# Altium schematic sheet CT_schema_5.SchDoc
size 281 x 146 mm
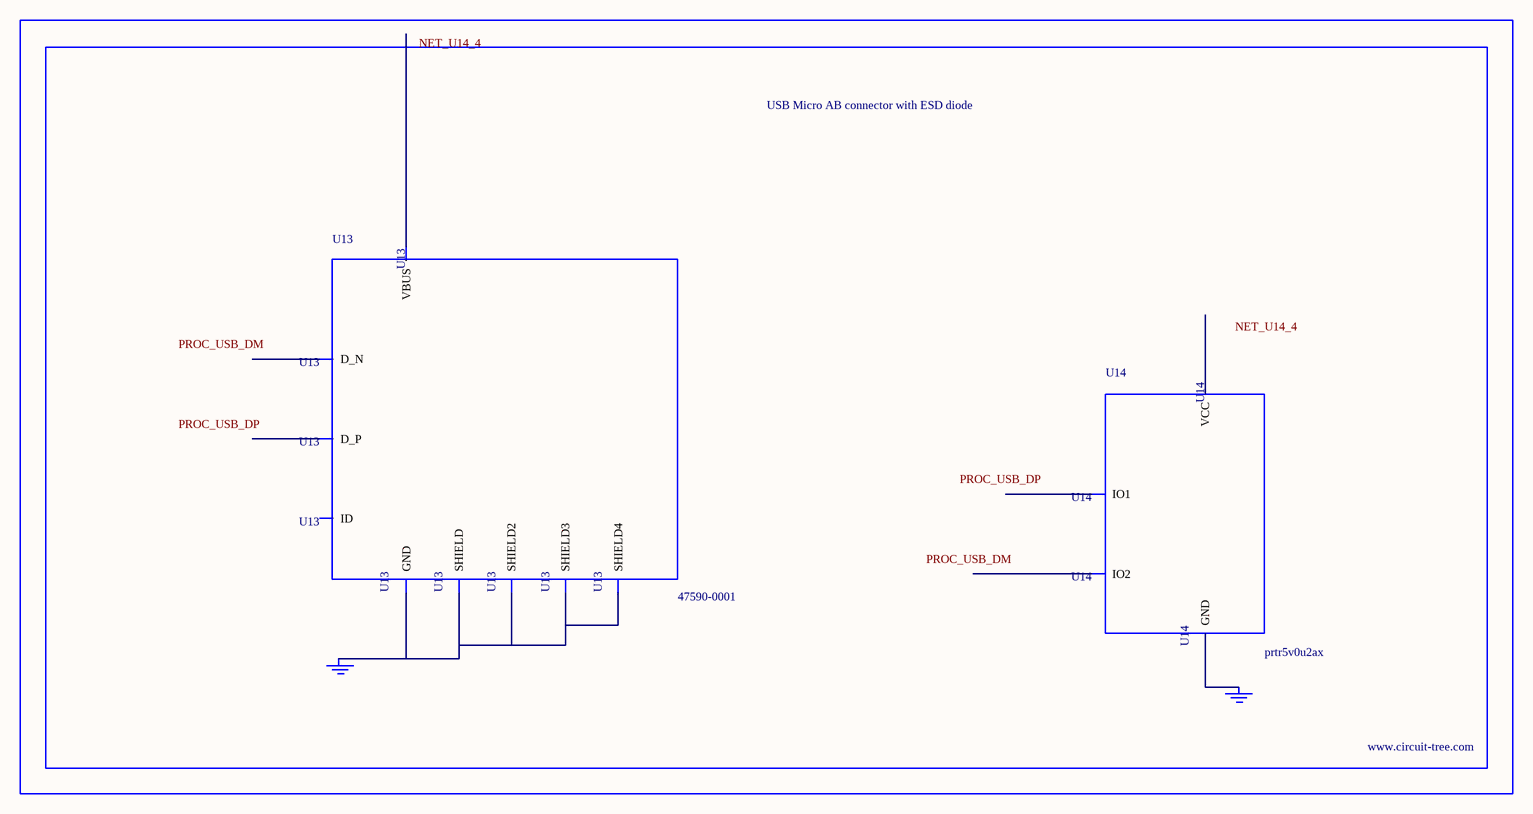
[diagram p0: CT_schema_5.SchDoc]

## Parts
BORDER4  (no value)
GND_INSTANCE_4_0  (no value)
GND_INSTANCE_4_1  (no value)
U13  47590-0001  [MICRO_USB_AB]
U14  prtr5v0u2ax  [SOT143B]

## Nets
NetGND_INSTANCE_4_0_0: GND_INSTANCE_4_0.0(GND) U13.5(GND) U13.6(SHIELD) U13.7(SHIELD2) U13.8(SHIELD3) U13.9(SHIELD4)
NetGND_INSTANCE_4_1_0: GND_INSTANCE_4_1.0(GND) U14.1(GND)

Not connected (* = marked no-connect by the designer): U13 1(VBUS) 2(D_N) 3(D_P) 4(ID); U14 2(IO1) 3(IO2) 4(VCC)

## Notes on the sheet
- Labels drawn without touching a wire or pin: NET_U14_4, PROC_USB_DM, PROC_USB_DP

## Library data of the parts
BORDER4 = BORDER_PAGE4
GND_INSTANCE_4_0 GND_INSTANCE_4_1 = GND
